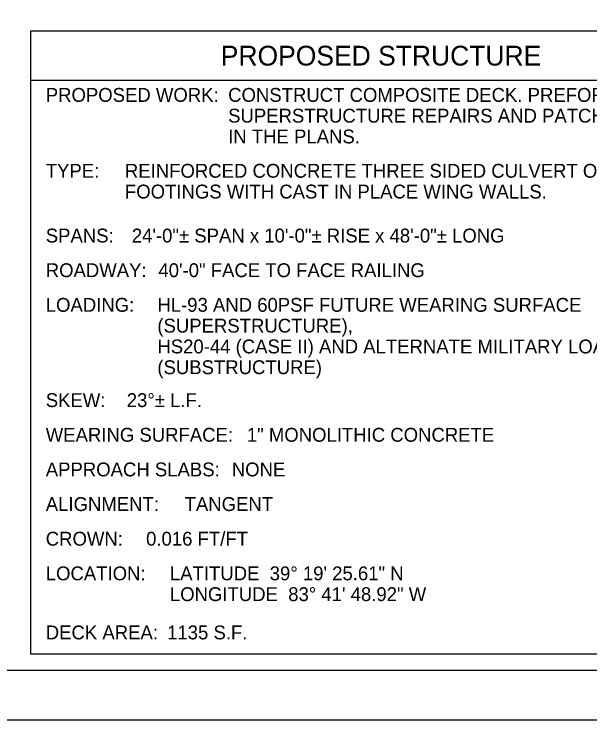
# Model space of a CAD drawing. Extents: x 0 to 680, y -49 to 440.
# Drawn here: x 491.6 to 608, y 0 to 142.6 of the extents above; entities that cross this region are included whole.
import ezdxf

# ---------------------------------------------------------------- set-up
doc = ezdxf.new("R2010")
doc.units = 0
for name, color, linetype in [('SN_X_Public', 7, 'Continuous'), ('SV_X_Shot_Marker', 7, 'Continuous'), ('UT_X_Misc_Cells', 7, 'Continuous'), ('VG_X_Cells', 7, 'Continuous')]:
    doc.layers.add(name, color=color, linetype=linetype)

msp = doc.modelspace()

# ---------------------------------------------------------------- linework, layer by layer
at = {"layer": 'SV_X_Shot_Marker'}
msp.add_lwpolyline([(30, 430), (670, 430), (670, 10), (30, 10)], close=True, dxfattribs=at)
at = {"layer": 'UT_X_Misc_Cells'}
msp.add_line((640, 129.2), (495, 129.2), dxfattribs=at)
msp.add_lwpolyline([(495, 139.2), (640, 139.2), (640, 13.27), (495, 13.27)], close=True, dxfattribs=at)
at = {"layer": 'VG_X_Cells'}
msp.add_lwpolyline([(0, 0), (680, 0), (680, 440), (0, 440)], close=True, dxfattribs=at)

# ---------------------------------------------------------------- texts
at = {"layer": 'SN_X_Public'}
for s, p in [('CONSTRUCT COMPOSITE DECK. PREFORM FULL DEPTH ', (534.87, 124.87)), ('SUPERSTRUCTURE REPAIRS AND PATCHING AS SHOWN ', (534.87, 120.67)), ('IN THE PLANS.', (534.87, 116.47)), ('REINFORCED CONCRETE THREE SIDED CULVERT ON CAST IN PLACE ', (514, 109.54)), ('FOOTINGS WITH CAST IN PLACE WING WALLS.', (514, 105.34)), ('24\'-0"± SPAN x 10\'-0"± RISE x 48\'-0"± LONG', (515.39, 96.45)), ('40\'-0" FACE TO FACE RAILING', (520.77, 89.45)), ('HL-93 AND 60PSF FUTURE WEARING SURFACE ', (520.56, 82.45)), ('(SUPERSTRUCTURE),', (520.56, 78.25)), ('HS20-44 (CASE II) AND ALTERNATE MILITARY LOADING ', (520.56, 74.05)), ('(SUBSTRUCTURE)', (520.56, 69.85)), ('23°± L.F.', (514.37, 63.2)), ('1" MONOLITHIC CONCRETE', (538.65, 56.2)), ('NONE', (535.61, 49.2)), ('TANGENT', (526.07, 42.2)), ('0.016 FT/FT', (518.28, 35.2)), ('LATITUDE  39° 19\' 25.61" N', (523.09, 28.2)), ('LONGITUDE  83° 41\' 48.92" W', (523.09, 24))]:
    msp.add_text(s, height=2.8, dxfattribs=at).set_placement(p)
at = {"layer": 'UT_X_Misc_Cells'}
for s, height, p in [('PROPOSED STRUCTURE', 4, (533.38, 132.2)), ('PROPOSED WORK:', 2.8, (498, 124.87)), ('TYPE:', 2.8, (498, 109.54)), ('SPANS:', 2.8, (498, 96.45)), ('ROADWAY:', 2.8, (498, 89.45)), ('LOADING:', 2.8, (498, 82.45)), ('SKEW:', 2.8, (498, 63.2)), ('WEARING SURFACE:', 2.8, (498, 56.2)), ('APPROACH SLABS:', 2.8, (498, 49.2)), ('ALIGNMENT:', 2.8, (498, 42.2)), ('CROWN:', 2.8, (498, 35.2)), ('LOCATION:', 2.8, (498, 28.2)), ('DECK AREA:', 2.8, (498, 16.27)), ('1135 S.F.', 2.8, (522.53, 16.27))]:
    msp.add_text(s, height=height, dxfattribs=at).set_placement(p)

doc.saveas('drawing.dxf')
